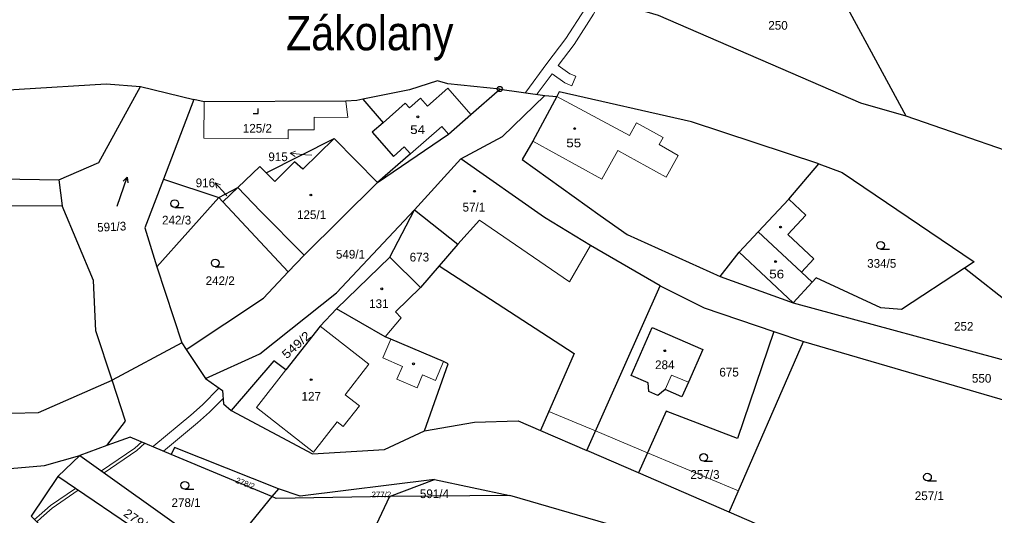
# Model space of a CAD drawing. Extents: x -754445 to -751443, y -1030748 to -1028224.
# Drawn here: x -753426.4 to -753236, y -1029333.7 to -1029236.8 of the extents above; entities that cross this region are included whole.
import ezdxf
from ezdxf.enums import TextEntityAlignment as Align

# ---------------------------------------------------------------- set-up
doc = ezdxf.new("R2010")
doc.units = 0
doc.header["$LTSCALE"] = 0.68
for name, color, linetype, lineweight in [('1', 7, 'Continuous', 25), ('13', 7, 'Continuous', 13), ('3', 7, 'Continuous', 25), ('4', 7, 'Continuous', 13), ('5', 7, 'Continuous', 25), ('7', 7, 'Continuous', 13), ('8', 7, 'Continuous', 25)]:
    doc.layers.add(name, color=color, linetype=linetype, lineweight=lineweight)
doc.layers.add('2', color=7, linetype='Continuous')

msp = doc.modelspace()

# ---------------------------------------------------------------- linework, layer by layer
at = {"layer": '1'}
for p, q in [((-753332.61, -1029250.42), (-753323.79, -1029251.71)), ((-753323.79, -1029251.71), (-753321.5, -1029251.88)), ((-753378.2, -1029266.81), (-753364.96, -1029260.09)), ((-753340.22, -1029264.08), (-753349.25, -1029274.01)), ((-753418.67, -1029268.18), (-753418.03, -1029273.2)), ((-753387.45, -1029271.63), (-753383.77, -1029269.64)), ((-753383.77, -1029269.64), (-753386.69, -1029272.45)), ((-753387.45, -1029271.63), (-753399.6, -1029285.14)), ((-753386.69, -1029272.45), (-753387.45, -1029271.63)), ((-753386.69, -1029272.45), (-753373.96, -1029286.14)), ((-753354.07, -1029283.25), (-753349.25, -1029274.01)), ((-753354.07, -1029283.25), (-753364.5, -1029293.37)), ((-753315.61, -1029321.01), (-753301.32, -1029288.86)), ((-753275.33, -1029292.14), (-753225.25, -1029305.78)), ((-753394.7, -1029300.01), (-753408.29, -1029307.28)), ((-753287.81, -1029333.07), (-753273.35, -1029299.73)), ((-753393.83, -1029301.31), (-753390.06, -1029306.96)), ((-753318.12, -1029302.05), (-753324.65, -1029317.09)), ((-753324.65, -1029317.09), (-753315.61, -1029321.01)), ((-753414.6, -1029321.97), (-753418.92, -1029326.06)), ((-753414.6, -1029321.97), (-753386.76, -1029341.81)), ((-753377.09, -1029330), (-753396.76, -1029321.76)), ((-753390.12, -1029345.58), (-753418.92, -1029326.06)), ((-753354.12, -1029329.96), (-753345.38, -1029326.68)), ((-753345.38, -1029326.68), (-753330.65, -1029329.77)), ((-753375.84, -1029328.48), (-753377.09, -1029330)), ((-753303.8, -1029337.61), (-753330.65, -1029329.77))]:
    msp.add_line(p, q, dxfattribs=at)
for points in [[(-753258.52, -1029218.5), (-753270.23, -1029224.51), (-753253.36, -1029255.67)], [(-753305.48, -1029234.87), (-753301.7, -1029235.97), (-753262.17, -1029253.13), (-753253.36, -1029255.67)], [(-753332.61, -1029250.42), (-753342.78, -1029249.43), (-753344.75, -1029248.83), (-753350.27, -1029250.55), (-753359.38, -1029252.43)], [(-753459.12, -1029250.43), (-753443.49, -1029251.47), (-753409.46, -1029249.43), (-753402.77, -1029249.93), (-753392.32, -1029252.46)], [(-753418.67, -1029268.18), (-753410.9, -1029264.75), (-753402.77, -1029249.93)], [(-753356.48, -1029268.65), (-753342.63, -1029259.23), (-753338.24, -1029255.37), (-753332.61, -1029250.42)], [(-753392.32, -1029252.46), (-753398.29, -1029268.03), (-753387.45, -1029271.63)], [(-753362.65, -1029252.8), (-753390.32, -1029252.94), (-753392.32, -1029252.46)], [(-753359.38, -1029252.43), (-753360.54, -1029252.67), (-753362.65, -1029252.8)], [(-753359.38, -1029252.43), (-753355.4, -1029256.99), (-753357.5, -1029258.83), (-753353.35, -1029263.57), (-753351.25, -1029261.73), (-753350.06, -1029263.08), (-753356.48, -1029268.65)], [(-753340.22, -1029264.08), (-753332.06, -1029259.67), (-753323.79, -1029251.71)], [(-753321.5, -1029251.88), (-753326.16, -1029260.57), (-753328.27, -1029264.2), (-753312.99, -1029275.14), (-753307.77, -1029278.85), (-753289.58, -1029287)], [(-753270.34, -1029265.01), (-753295.21, -1029256.8), (-753321.03, -1029251), (-753321.5, -1029251.88)], [(-753253.36, -1029255.67), (-753223.22, -1029266.09), (-753206.72, -1029275.86), (-753199.5, -1029271.03)], [(-753364.96, -1029260.09), (-753371.05, -1029266.1), (-753372.66, -1029264.63), (-753376.52, -1029268.49), (-753378.2, -1029266.81)], [(-753373.96, -1029286.14), (-753370.8, -1029282.86), (-753356.48, -1029268.65), (-753364.96, -1029260.09)], [(-753301.32, -1029288.86), (-753314.9, -1029280.95), (-753323.9, -1029275.54), (-753340.22, -1029264.08)], [(-753378.2, -1029266.81), (-753379.49, -1029265.52), (-753383.77, -1029269.64)], [(-753289.58, -1029287), (-753285.88, -1029282.27), (-753282.15, -1029278.28), (-753276.19, -1029271.91), (-753270.34, -1029265.01)], [(-753270.34, -1029265.01), (-753265.75, -1029266.69), (-753239.98, -1029284.14), (-753241.88, -1029285.39)], [(-753462.02, -1029270.37), (-753441.51, -1029267.75), (-753418.67, -1029268.18)], [(-753398.29, -1029268.03), (-753401.93, -1029277.54), (-753399.6, -1029285.14)], [(-753418.03, -1029273.2), (-753470.13, -1029273.54), (-753485.96, -1029286.37)], [(-753408.29, -1029307.28), (-753411.47, -1029297.63), (-753411.91, -1029287.8), (-753418.03, -1029273.2)], [(-753271.6, -1029288.15), (-753273.72, -1029286.17), (-753271.31, -1029283.6), (-753276.39, -1029278.85), (-753272.84, -1029275.06), (-753276.19, -1029271.91)], [(-753390.06, -1029306.96), (-753379.43, -1029302.16), (-753364.52, -1029290.19), (-753349.25, -1029274.01)], [(-753349.25, -1029274.01), (-753340.83, -1029280.72), (-753344.48, -1029284.95), (-753318.12, -1029302.05)], [(-753344.48, -1029284.95), (-753348.12, -1029289.19), (-753354.07, -1029283.25)], [(-753399.6, -1029285.14), (-753394.7, -1029300.01), (-753393.83, -1029301.31)], [(-753485.96, -1029286.37), (-753445.42, -1029309.07), (-753433.26, -1029313.83), (-753422.66, -1029313.58), (-753408.29, -1029307.28)], [(-753393.83, -1029301.31), (-753378.72, -1029291.29), (-753373.96, -1029286.14)], [(-753289.58, -1029287), (-753275.33, -1029292.14), (-753271.6, -1029288.15)], [(-753241.88, -1029285.39), (-753254.19, -1029293.46), (-753258.2, -1029293.13), (-753270.83, -1029287.32), (-753271.6, -1029288.15)], [(-753225.25, -1029305.78), (-753223.01, -1029300.22), (-753241.88, -1029285.39)], [(-753301.32, -1029288.86), (-753292.69, -1029293.16), (-753279.12, -1029297.77), (-753273.35, -1029299.73)], [(-753364.5, -1029293.37), (-753367.7, -1029296.72), (-753374.38, -1029305.28), (-753376.7, -1029303.48), (-753385.06, -1029313.21)], [(-753347.31, -1029317.16), (-753342.67, -1029304.05), (-753343.61, -1029303.65), (-753353.89, -1029299.25), (-753354.97, -1029298.78), (-753364.5, -1029293.37)], [(-753279.12, -1029297.77), (-753286.22, -1029318.69), (-753300.15, -1029313.33), (-753305.51, -1029325.39)], [(-753273.35, -1029299.73), (-753229.21, -1029312.62), (-753221.68, -1029314.7), (-753211.16, -1029319.1), (-753198.69, -1029326.32), (-753193.68, -1029328.26)], [(-753409.31, -1029320.05), (-753405.68, -1029315.26), (-753408.29, -1029307.28)], [(-753390.06, -1029306.96), (-753386.76, -1029309.31), (-753386.56, -1029311.9), (-753385.06, -1029313.21)], [(-753454.9, -1029312.86), (-753434.23, -1029325.07), (-753421.49, -1029323.94), (-753414.6, -1029321.97)], [(-753385.06, -1029313.21), (-753369.21, -1029321.63), (-753355.13, -1029320.82), (-753347.31, -1029317.16)], [(-753347.31, -1029317.16), (-753337.53, -1029315.5), (-753329.01, -1029315.2), (-753324.65, -1029317.09)], [(-753396.76, -1029321.76), (-753404.76, -1029318.4), (-753409.31, -1029320.05), (-753414.6, -1029321.97)], [(-753375.84, -1029328.48), (-753396.13, -1029320.44), (-753396.76, -1029321.76)], [(-753287.81, -1029333.07), (-753305.51, -1029325.39), (-753315.61, -1029321.01)], [(-753418.92, -1029326.06), (-753424.13, -1029333.8), (-753400.65, -1029357.37)], [(-753345.38, -1029326.68), (-753371.61, -1029329.91), (-753375.84, -1029328.48)], [(-753354.12, -1029329.96), (-753376.24, -1029330.36), (-753377.09, -1029330), (-753386.76, -1029341.81)], [(-753330.65, -1029329.77), (-753354.12, -1029329.96), (-753362.04, -1029346.69)], [(-753183.7, -1029342.08), (-753190.21, -1029342.56), (-753220.07, -1029352.09), (-753245.1, -1029351.6), (-753287.81, -1029333.07)]]:
    msp.add_lwpolyline(points, dxfattribs=at)
msp.add_lwpolyline([(-753293, -1029301.29), (-753295.78, -1029307.67), (-753297.07, -1029310.55), (-753300.34, -1029309.12), (-753301.76, -1029310.25), (-753303.5, -1029309.46), (-753303.65, -1029307.8), (-753306.94, -1029306.34), (-753302.85, -1029296.98)], close=True, dxfattribs=at)
at = {"layer": '13'}
for points in [[(-753319.75, -1029240.58), (-753323.43, -1029245.46), (-753327.56, -1029251.04), (-753327.64, -1029251.15), (-753325.39, -1029251.48), (-753325.13, -1029251.12), (-753322.41, -1029247.45), (-753319.93, -1029249.24), (-753318.54, -1029249.8), (-753317.8, -1029247.94), (-753318.95, -1029247.48), (-753321.22, -1029245.85), (-753318.11, -1029241.72), (-753314.29, -1029235.83), (-753312.73, -1029232.98), (-753312.62, -1029232.81), (-753314.6, -1029232.23), (-753314.69, -1029232.39), (-753316.01, -1029234.81)], [(-753389.27, -1029313.53), (-753386.64, -1029310.85), (-753386.76, -1029309.31), (-753387.45, -1029308.82), (-753390.65, -1029312.07), (-753392.94, -1029314.1), (-753400.15, -1029320.11), (-753400.33, -1029320.26), (-753398.25, -1029321.13), (-753391.64, -1029315.62)], [(-753323.04, -1029313.37), (-753324.65, -1029317.09), (-753315.61, -1029321.01), (-753313.91, -1029317.18)], [(-753303.75, -1029321.43), (-753313.91, -1029317.18), (-753315.61, -1029321.01), (-753305.51, -1029325.39), (-753287.81, -1029333.07), (-753285.99, -1029328.85)], [(-753403.86, -1029320.55), (-753410.39, -1029324.97), (-753409.87, -1029325.34), (-753403.5, -1029321.03), (-753401.89, -1029319.6), (-753402.51, -1029319.34)], [(-753422.56, -1029333.68), (-753423.44, -1029334.47), (-753423.01, -1029334.91), (-753422.16, -1029334.14), (-753419.97, -1029332.25), (-753414.92, -1029328.77), (-753415.46, -1029328.41), (-753420.33, -1029331.77)]]:
    msp.add_lwpolyline(points, close=True, dxfattribs=at)
at = {"layer": '3'}
for p, q in [((-753405.36, -1029267.62), (-753405.204, -1029268.707)), ((-753396.083, -1029273.54), (-753394.333, -1029273.54)), ((-753258.273, -1029281.69), (-753256.523, -1029281.69)), ((-753388.163, -1029285.14), (-753386.413, -1029285.14)), ((-753292.813, -1029323.11), (-753291.063, -1029323.11)), ((-753249.123, -1029326.95), (-753247.373, -1029326.95)), ((-753394.103, -1029328.55), (-753392.353, -1029328.55))]:
    msp.add_line(p, q, dxfattribs=at)
for points in [[(-753380.761, -1029255.21), (-753379.76, -1029255.21), (-753379.76, -1029254.21)], [(-753407.313, -1029273.293), (-753405.36, -1029267.62), (-753406.152, -1029268.381)]]:
    msp.add_lwpolyline(points, dxfattribs=at)
for centre in [(-753396.0829, -1029272.7898), (-753258.2729, -1029280.9398), (-753388.1629, -1029284.3898), (-753292.8129, -1029322.3598), (-753394.1029, -1029327.7998), (-753249.1229, -1029326.1998)]:
    msp.add_circle(centre, 0.75, dxfattribs=at)
at = {"layer": '4'}
for p, q in [((-753346.71, -1029253.76), (-753342.73, -1029250.26)), ((-753342.73, -1029250.26), (-753338.24, -1029255.37)), ((-753362.65, -1029252.8), (-753362.3, -1029255.98)), ((-753350.27, -1029254.1), (-753348.1, -1029252.19)), ((-753348.1, -1029252.19), (-753346.71, -1029253.76)), ((-753307.28, -1029259.5), (-753321.5, -1029251.88)), ((-753390.32, -1029252.94), (-753390.39, -1029260)), ((-753351.07, -1029253.2), (-753355.4, -1029256.99)), ((-753351.07, -1029253.2), (-753350.27, -1029254.1)), ((-753368.85, -1029255.91), (-753368.87, -1029258.41)), ((-753362.3, -1029255.98), (-753368.85, -1029255.91)), ((-753373.92, -1029258.36), (-753373.94, -1029260.16)), ((-753368.87, -1029258.41), (-753373.92, -1029258.36)), ((-753350.06, -1029263.08), (-753343.95, -1029257.73)), ((-753343.95, -1029257.73), (-753342.63, -1029259.23)), ((-753307.28, -1029259.5), (-753305.91, -1029257.03)), ((-753305.91, -1029257.03), (-753300.75, -1029259.88)), ((-753373.94, -1029260.16), (-753390.39, -1029260)), ((-753300.75, -1029259.88), (-753301.53, -1029261.28)), ((-753312.68, -1029268.03), (-753326.16, -1029260.57)), ((-753301.53, -1029261.28), (-753297.76, -1029263.37)), ((-753309.59, -1029262.43), (-753312.68, -1029268.03)), ((-753300.14, -1029267.65), (-753309.59, -1029262.43)), ((-753297.76, -1029263.37), (-753300.14, -1029267.65)), ((-753383.77, -1029269.64), (-753379.32, -1029274.27)), ((-753379.32, -1029274.27), (-753370.8, -1029282.86)), ((-753340.83, -1029280.72), (-753336.57, -1029276.04)), ((-753336.57, -1029276.04), (-753319.03, -1029288.06)), ((-753282.15, -1029278.28), (-753273.72, -1029286.17)), ((-753319.03, -1029288.06), (-753314.9, -1029280.95)), ((-753275.33, -1029292.14), (-753285.88, -1029282.27)), ((-753348.12, -1029289.19), (-753353, -1029293.92)), ((-753351.89, -1029295.07), (-753353, -1029293.92)), ((-753351.89, -1029295.07), (-753354.97, -1029298.78)), ((-753358.16, -1029304.16), (-753367.7, -1029296.72)), ((-753353.89, -1029299.25), (-753355.47, -1029302.94)), ((-753362.81, -1029310.12), (-753358.16, -1029304.16)), ((-753355.47, -1029302.94), (-753351.64, -1029304.57)), ((-753345.18, -1029307.34), (-753343.61, -1029303.65)), ((-753374.38, -1029305.28), (-753380.1, -1029312.61)), ((-753352.71, -1029307.06), (-753351.64, -1029304.57)), ((-753348.76, -1029308.75), (-753352.71, -1029307.06)), ((-753347.7, -1029306.26), (-753348.76, -1029308.75)), ((-753347.7, -1029306.26), (-753345.18, -1029307.34)), ((-753300.34, -1029309.12), (-753299.08, -1029306.27)), ((-753299.08, -1029306.27), (-753295.78, -1029307.67)), ((-753360.02, -1029312.29), (-753362.81, -1029310.12)), ((-753368.96, -1029321.31), (-753380.1, -1029312.61)), ((-753363.16, -1029316.31), (-753360.02, -1029312.29)), ((-753368.96, -1029321.31), (-753364.34, -1029315.39)), ((-753364.34, -1029315.39), (-753363.16, -1029316.31))]:
    msp.add_line(p, q, dxfattribs=at)
at = {"layer": '5'}
for centre in [(-753348.6168, -1029255.8392), (-753317.9968, -1029258.1492), (-753369.4868, -1029271.1192), (-753337.5468, -1029270.3792), (-753277.7968, -1029277.3792), (-753278.7768, -1029284.1192), (-753355.6668, -1029289.4392), (-753300.4068, -1029301.5292), (-753349.4568, -1029304.0892), (-753369.4268, -1029307.1792)]:
    msp.add_circle(centre, 0.175, dxfattribs=at)
at = {"layer": '7'}
for p, q in [((-753373.52, -1029262.978), (-753372.566, -1029263.565)), ((-753388.178, -1029268.73), (-753387.88, -1029269.809))]:
    msp.add_line(p, q, dxfattribs=at)
for points in [[(-753369.28, -1029263.35), (-753370.53, -1029263.24), (-753373.52, -1029262.978), (-753372.478, -1029262.567)], [(-753385.89, -1029271.27), (-753386.17, -1029270.96), (-753388.178, -1029268.73), (-753387.136, -1029269.139)]]:
    msp.add_lwpolyline(points, dxfattribs=at)
at = {"layer": '8'}
for radius in [0.5, 0.0303]:
    msp.add_circle((-753332.61, -1029250.4199), radius, dxfattribs=at)

# ---------------------------------------------------------------- texts
at = {"layer": '2'}
for s, height, p in [('250', 1.7, (-753278.299, -1029238.84)), ('125/2', 1.7, (-753379.94, -1029258.94)), ('915', 1.7, (-753375.899, -1029264.5)), ('57/1', 1.7, (-753337.67, -1029274.34)), ('242/3', 1.7, (-753395.71, -1029276.87)), ('125/1', 1.7, (-753369.36, -1029275.81)), ('549/1', 1.7, (-753361.76, -1029283.53)), ('673', 1.7, (-753348.309, -1029284.1)), ('334/5', 1.7, (-753258.05, -1029285.32)), ('242/2', 1.7, (-753387.2, -1029288.7)), ('131', 1.7, (-753356.229, -1029293.19)), ('252', 1.7, (-753242.049, -1029297.61)), ('284', 1.7, (-753300.399, -1029305.12)), ('675', 1.7, (-753287.849, -1029306.56)), ('550', 1.7, (-753238.549, -1029307.76)), ('127', 1.7, (-753369.419, -1029311.27)), ('257/3', 1.7, (-753292.56, -1029326.54)), ('277/2', 1.14, (-753355.719, -1029330.17)), ('591/4', 1.7, (-753345.37, -1029330.3)), ('257/1', 1.7, (-753248.75, -1029330.69)), ('278/1', 1.7, (-753393.86, -1029332.04))]:
    msp.add_text(s, height=height, dxfattribs=at).set_placement(p, align=Align.CENTER)
at = {"layer": '2', "width": 1.15}
for s, p in [('54', (-753348.66, -1029259.2)), ('55', (-753318.18, -1029261.8)), ('56', (-753278.56, -1029287.4))]:
    msp.add_text(s, height=1.7, dxfattribs=at).set_placement(p, align=Align.CENTER)
at = {"layer": '2'}
msp.add_text('916', height=1.7, dxfattribs=at).set_placement((-753388.189, -1029269.59), align=Align.RIGHT)
for s, height, rotation, p in [('591/3', 1.7, 3, (-753408.336, -1029278.1563)), ('278/2', 1.14, 339, (-753382.5173, -1029327.9539))]:
    msp.add_text(s, height=height, rotation=rotation, dxfattribs=at).set_placement(p, align=Align.CENTER)
for s, rotation, width, p in [('549/2', 42, 1.15, (-753371.7818, -1029301.0198)), ('279/3', 325, 1.1, (-753403.6725, -1029335.4331))]:
    msp.add_text(s, height=1.7, rotation=rotation, dxfattribs=dict(at, width=width)).set_placement(p, align=Align.CENTER)
at = {"layer": '7', "width": 0.9}
msp.add_text('Zákolany', height=6.7, dxfattribs=at).set_placement((-753358.01, -1029242.856), align=Align.CENTER)

doc.saveas('drawing.dxf')
